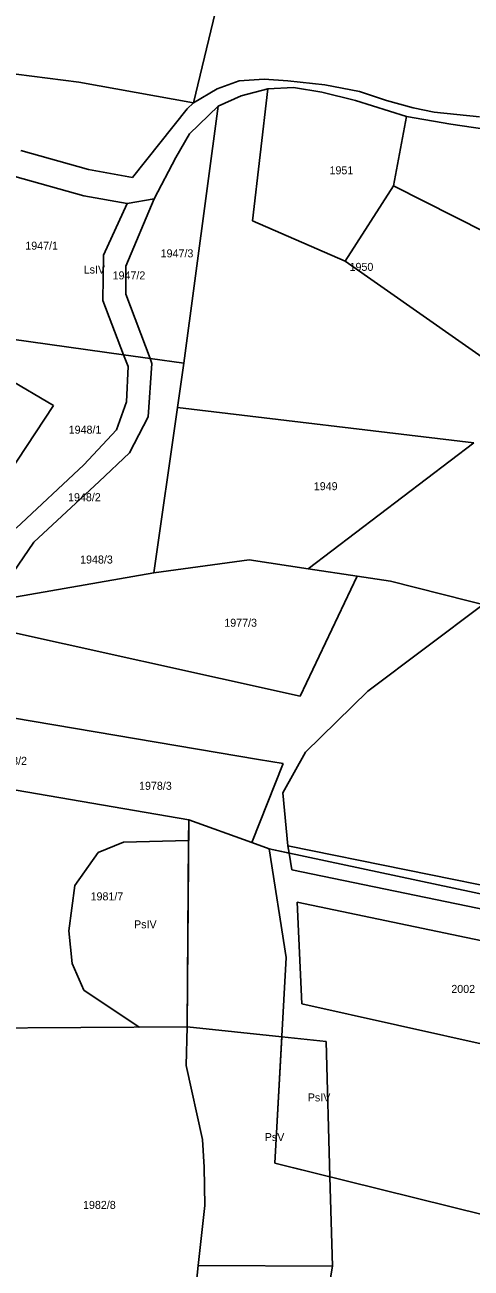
# Model space of a CAD drawing. Extents: x 7498273 to 7499989, y 5499795 to 5500810.
# Drawn here: x 7499197.4 to 7499281.1, y 5499981.8 to 5500214.9 of the extents above; entities that cross this region are included whole.
import ezdxf

# ---------------------------------------------------------------- set-up
doc = ezdxf.new("R2010")
doc.units = 0
for name, color, linetype in [('209-oznaczenie konturu klasyfikacyjnego', 7, 'Continuous'), ('211-numer działki ewidencyjnej', 7, 'Continuous'), ('217-kontur klasyfikacyjny', 7, 'Continuous'), ('218-kontur użytku gruntowego', 7, 'Continuous'), ('219-działka ewidencyjna', 7, 'Continuous')]:
    doc.layers.add(name, color=color, linetype=linetype)

msp = doc.modelspace()

# ---------------------------------------------------------------- linework, layer by layer
at = {"layer": '217-kontur klasyfikacyjny'}
for points in [[(7499229.03, 5500200.27), (7499235.12, 5500225.77)], [(7499186.88, 5500206.79), (7499207.52, 5500204.16)], [(7499207.52, 5500204.16), (7499229.03, 5500200.27)], [(7499229.03, 5500200.27), (7499233.47, 5500202.91)], [(7499233.47, 5500202.91), (7499237.55, 5500204.4)], [(7499237.55, 5500204.4), (7499242.29, 5500204.73)], [(7499242.97, 5500202.88), (7499237.94, 5500201.57)], [(7499242.97, 5500202.88), (7499240.05, 5500178.17)], [(7499242.29, 5500204.73), (7499246.68, 5500204.41)], [(7499247.76, 5500203.13), (7499242.97, 5500202.88)], [(7499246.68, 5500204.41), (7499253.65, 5500203.66)], [(7499253.08, 5500202.29), (7499247.76, 5500203.13)], [(7499253.65, 5500203.66), (7499260.14, 5500202.4)], [(7499229.03, 5500200.27), (7499227.83, 5500199.13)], [(7499237.94, 5500201.57), (7499233.63, 5500199.67)], [(7499259.41, 5500200.69), (7499253.08, 5500202.29)], [(7499268.98, 5500197.72), (7499259.41, 5500200.69)], [(7499260.14, 5500202.4), (7499265.22, 5500200.7)], [(7499265.22, 5500200.7), (7499270.23, 5500199.31)], [(7499227.83, 5500199.13), (7499217.53, 5500186.26)], [(7499233.63, 5500199.67), (7499228.26, 5500194.46)], [(7499270.23, 5500199.31), (7499274.15, 5500198.51)], [(7499274.15, 5500198.51), (7499282.68, 5500197.66)], [(7499277.25, 5500196.3), (7499268.98, 5500197.72)], [(7499283.63, 5500195.35), (7499277.25, 5500196.3)], [(7499228.26, 5500194.46), (7499225.67, 5500190.03)], [(7499209.3, 5500187.74), (7499196.63, 5500191.33)], [(7499225.67, 5500190.03), (7499221.6, 5500182.29)], [(7499208.43, 5500182.85), (7499195.49, 5500186.46)], [(7499217.53, 5500186.26), (7499209.3, 5500187.74)], [(7499216.55, 5500181.37), (7499208.43, 5500182.85)], [(7499221.6, 5500182.29), (7499216.55, 5500181.37)], [(7499240.05, 5500178.17), (7499257.43, 5500170.6)], [(7499257.43, 5500170.6), (7499293.39, 5500145.42)], [(7499283.33, 5500106.19), (7499261.72, 5500089.98)], [(7499261.72, 5500089.98), (7499250, 5500078.53)], [(7499250, 5500078.53), (7499245.79, 5500070.94)], [(7499245.79, 5500070.94), (7499246.69, 5500061)], [(7499228.12, 5500065.83), (7499228.09, 5500062)], [(7499239.94, 5500061.63), (7499228.12, 5500065.83)], [(7499215.88, 5500061.66), (7499211.12, 5500059.72)], [(7499228.09, 5500062), (7499215.88, 5500061.66)], [(7499227.79, 5500027.07), (7499228.09, 5500062)], [(7499243.19, 5500060.39), (7499239.94, 5500061.63)], [(7499246.92, 5500059.6), (7499243.19, 5500060.39)], [(7499246.69, 5500061), (7499291.1, 5500051.95)], [(7499246.69, 5500061), (7499246.92, 5500059.6)], [(7499211.12, 5500059.72), (7499206.77, 5500053.52)], [(7499247.42, 5500056.48), (7499246.92, 5500059.6)], [(7499297.7, 5500046.12), (7499247.42, 5500056.48)], [(7499206.77, 5500053.52), (7499205.6, 5500045.03)], [(7499205.6, 5500045.03), (7499206.22, 5500038.89)], [(7499206.22, 5500038.89), (7499208.41, 5500033.9)], [(7499208.41, 5500033.9), (7499218.8, 5500027.01)], [(7499218.8, 5500027.01), (7499227.79, 5500027.07)], [(7499227.79, 5500027.07), (7499227.65, 5500019.78)], [(7499227.79, 5500027.07), (7499245.56, 5500025.18)], [(7499244.27, 5500001.51), (7499245.56, 5500025.18)], [(7499245.56, 5500025.18), (7499253.87, 5500024.29)], [(7499253.87, 5500024.29), (7499254.6, 5499998.94)], [(7499227.65, 5500019.78), (7499230.67, 5500005.9)], [(7499230.67, 5500005.9), (7499231.02, 5500000.74)], [(7499231.02, 5500000.74), (7499231.16, 5499993.55)], [(7499254.6, 5499998.94), (7499244.27, 5500001.51)], [(7499254.6, 5499998.94), (7499255.09, 5499982.18)], [(7499231.16, 5499993.55), (7499229.91, 5499982.27)], [(7499229.91, 5499982.27), (7499227.42, 5499958.75)], [(7499255.09, 5499982.18), (7499229.91, 5499982.27)]]:
    msp.add_lwpolyline(points, dxfattribs=at)
at = {"layer": '218-kontur użytku gruntowego'}
for points in [[(7499235.12, 5500225.77), (7499229.03, 5500200.27)], [(7499186.88, 5500206.79), (7499207.52, 5500204.16)], [(7499207.52, 5500204.16), (7499229.03, 5500200.27)], [(7499229.03, 5500200.27), (7499233.47, 5500202.91)], [(7499233.47, 5500202.91), (7499237.55, 5500204.4)], [(7499237.55, 5500204.4), (7499242.29, 5500204.73)], [(7499242.97, 5500202.88), (7499237.94, 5500201.57)], [(7499242.97, 5500202.88), (7499240.05, 5500178.17)], [(7499242.29, 5500204.73), (7499246.68, 5500204.41)], [(7499247.76, 5500203.13), (7499242.97, 5500202.88)], [(7499246.68, 5500204.41), (7499253.65, 5500203.66)], [(7499253.08, 5500202.29), (7499247.76, 5500203.13)], [(7499253.65, 5500203.66), (7499260.14, 5500202.4)], [(7499229.03, 5500200.27), (7499227.83, 5500199.13)], [(7499237.94, 5500201.57), (7499233.63, 5500199.67)], [(7499259.41, 5500200.69), (7499253.08, 5500202.29)], [(7499268.98, 5500197.72), (7499259.41, 5500200.69)], [(7499260.14, 5500202.4), (7499265.22, 5500200.7)], [(7499265.22, 5500200.7), (7499270.23, 5500199.31)], [(7499227.83, 5500199.13), (7499217.53, 5500186.26)], [(7499233.63, 5500199.67), (7499228.26, 5500194.46)], [(7499270.23, 5500199.31), (7499274.15, 5500198.51)], [(7499274.15, 5500198.51), (7499282.68, 5500197.66)], [(7499277.25, 5500196.3), (7499268.98, 5500197.72)], [(7499283.63, 5500195.35), (7499277.25, 5500196.3)], [(7499228.26, 5500194.46), (7499225.67, 5500190.03)], [(7499209.3, 5500187.74), (7499196.63, 5500191.33)], [(7499225.67, 5500190.03), (7499221.6, 5500182.29)], [(7499208.43, 5500182.85), (7499195.49, 5500186.46)], [(7499217.53, 5500186.26), (7499209.3, 5500187.74)], [(7499216.55, 5500181.37), (7499208.43, 5500182.85)], [(7499221.6, 5500182.29), (7499216.55, 5500181.37)], [(7499240.05, 5500178.17), (7499257.43, 5500170.6)], [(7499257.43, 5500170.6), (7499293.39, 5500145.42)], [(7499283.33, 5500106.19), (7499261.72, 5500089.98)], [(7499261.72, 5500089.98), (7499250, 5500078.53)], [(7499250, 5500078.53), (7499245.79, 5500070.94)], [(7499245.79, 5500070.94), (7499246.69, 5500061)], [(7499228.12, 5500065.83), (7499228.09, 5500062)], [(7499239.94, 5500061.63), (7499228.12, 5500065.83)], [(7499215.88, 5500061.66), (7499211.12, 5500059.72)], [(7499228.09, 5500062), (7499215.88, 5500061.66)], [(7499228.09, 5500062), (7499227.79, 5500027.07)], [(7499243.19, 5500060.39), (7499239.94, 5500061.63)], [(7499246.92, 5500059.6), (7499243.19, 5500060.39)], [(7499246.69, 5500061), (7499291.1, 5500051.95)], [(7499246.69, 5500061), (7499246.92, 5500059.6)], [(7499211.12, 5500059.72), (7499206.77, 5500053.52)], [(7499246.92, 5500059.6), (7499247.42, 5500056.48)], [(7499247.42, 5500056.48), (7499297.7, 5500046.12)], [(7499206.77, 5500053.52), (7499205.6, 5500045.03)], [(7499205.6, 5500045.03), (7499206.22, 5500038.89)], [(7499206.22, 5500038.89), (7499208.41, 5500033.9)], [(7499208.41, 5500033.9), (7499218.8, 5500027.01)], [(7499218.8, 5500027.01), (7499227.79, 5500027.07)], [(7499227.79, 5500027.07), (7499227.65, 5500019.78)], [(7499227.79, 5500027.07), (7499245.56, 5500025.18)], [(7499245.56, 5500025.18), (7499244.27, 5500001.51)], [(7499253.87, 5500024.29), (7499245.56, 5500025.18)], [(7499254.6, 5499998.94), (7499253.87, 5500024.29)], [(7499227.65, 5500019.78), (7499230.67, 5500005.9)], [(7499230.67, 5500005.9), (7499231.02, 5500000.74)], [(7499231.02, 5500000.74), (7499231.16, 5499993.55)], [(7499244.27, 5500001.51), (7499254.6, 5499998.94)], [(7499254.6, 5499998.94), (7499255.09, 5499982.18)], [(7499231.16, 5499993.55), (7499229.91, 5499982.27)], [(7499229.91, 5499982.27), (7499227.42, 5499958.75)], [(7499255.09, 5499982.18), (7499229.91, 5499982.27)]]:
    msp.add_lwpolyline(points, dxfattribs=at)
at = {"layer": '219-działka ewidencyjna'}
for points in [[(7499229.03, 5500200.27), (7499235.12, 5500225.77)], [(7499186.88, 5500206.79), (7499207.52, 5500204.16)], [(7499207.52, 5500204.16), (7499229.03, 5500200.27)], [(7499229.03, 5500200.27), (7499233.47, 5500202.91)], [(7499233.47, 5500202.91), (7499237.55, 5500204.4)], [(7499237.55, 5500204.4), (7499242.29, 5500204.73)], [(7499237.94, 5500201.57), (7499242.97, 5500202.88)], [(7499240.05, 5500178.17), (7499242.97, 5500202.88)], [(7499242.29, 5500204.73), (7499246.68, 5500204.41)], [(7499247.76, 5500203.13), (7499242.97, 5500202.88)], [(7499246.68, 5500204.41), (7499253.65, 5500203.66)], [(7499247.76, 5500203.13), (7499253.08, 5500202.29)], [(7499253.65, 5500203.66), (7499260.14, 5500202.4)], [(7499229.03, 5500200.27), (7499227.83, 5500199.13)], [(7499233.63, 5500199.67), (7499237.94, 5500201.57)], [(7499253.08, 5500202.29), (7499259.41, 5500200.69)], [(7499259.41, 5500200.69), (7499268.98, 5500197.72)], [(7499260.14, 5500202.4), (7499265.22, 5500200.7)], [(7499265.22, 5500200.7), (7499270.23, 5500199.31)], [(7499217.53, 5500186.26), (7499227.83, 5500199.13)], [(7499227.21, 5500151.46), (7499233.63, 5500199.67)], [(7499233.63, 5500199.67), (7499228.26, 5500194.46)], [(7499270.23, 5500199.31), (7499274.15, 5500198.51)], [(7499274.15, 5500198.51), (7499282.68, 5500197.66)], [(7499268.98, 5500197.72), (7499266.51, 5500184.72)], [(7499268.98, 5500197.72), (7499277.25, 5500196.3)], [(7499277.25, 5500196.3), (7499283.63, 5500195.35)], [(7499225.67, 5500190.03), (7499228.26, 5500194.46)], [(7499196.63, 5500191.33), (7499209.3, 5500187.74)], [(7499221.6, 5500182.29), (7499225.67, 5500190.03)], [(7499195.49, 5500186.46), (7499208.43, 5500182.85)], [(7499209.3, 5500187.74), (7499217.53, 5500186.26)], [(7499257.43, 5500170.6), (7499266.51, 5500184.72)], [(7499295.36, 5500170.12), (7499266.51, 5500184.72)], [(7499208.43, 5500182.85), (7499216.55, 5500181.37)], [(7499221.6, 5500182.29), (7499216.31, 5500169.66)], [(7499216.55, 5500181.37), (7499221.6, 5500182.29)], [(7499216.55, 5500181.37), (7499212.15, 5500171.7)], [(7499240.05, 5500178.17), (7499257.43, 5500170.6)], [(7499211.98, 5500163.24), (7499212.15, 5500171.7)], [(7499257.43, 5500170.6), (7499293.39, 5500145.42)], [(7499216.3, 5500164.43), (7499216.31, 5500169.66)], [(7499215.88, 5500153.04), (7499211.98, 5500163.24)], [(7499220.85, 5500152.35), (7499216.3, 5500164.43)], [(7499187.72, 5500156.98), (7499215.88, 5500153.04)], [(7499215.88, 5500153.04), (7499220.85, 5500152.35)], [(7499215.88, 5500153.04), (7499216.72, 5500150.85)], [(7499220.52, 5500141.42), (7499221.2, 5500151.41)], [(7499220.85, 5500152.35), (7499221.2, 5500151.41)], [(7499227.21, 5500151.46), (7499220.85, 5500152.35)], [(7499226.03, 5500143.16), (7499227.21, 5500151.46)], [(7499216.45, 5500144.23), (7499216.72, 5500150.85)], [(7499194.03, 5500148.64), (7499202.75, 5500143.55)], [(7499194.32, 5500130.74), (7499202.75, 5500143.55)], [(7499214.54, 5500138.99), (7499216.45, 5500144.23)], [(7499221.56, 5500112.14), (7499226.03, 5500143.16)], [(7499226.03, 5500143.16), (7499281.57, 5500136.52)], [(7499216.98, 5500134.65), (7499220.52, 5500141.42)], [(7499208.44, 5500132.43), (7499214.54, 5500138.99)], [(7499250.49, 5500112.93), (7499281.57, 5500136.52)], [(7499211.3, 5500129.27), (7499216.98, 5500134.65)], [(7499195.73, 5500120.55), (7499208.44, 5500132.43)], [(7499199.04, 5500117.9), (7499211.3, 5500129.27)], [(7499192.18, 5500107.88), (7499199.04, 5500117.9)], [(7499239.47, 5500114.6), (7499221.56, 5500112.14)], [(7499239.47, 5500114.6), (7499250.49, 5500112.93)], [(7499221.56, 5500112.14), (7499191.8, 5500106.98)], [(7499250.49, 5500112.93), (7499259.68, 5500111.51)], [(7499259.68, 5500111.51), (7499248.99, 5500089.05)], [(7499259.68, 5500111.51), (7499265.93, 5500110.61)], [(7499265.93, 5500110.61), (7499290.4, 5500104.39)], [(7499248.99, 5500089.05), (7499189.74, 5500102.18)], [(7499241.2, 5500077.18), (7499191.28, 5500085.61)], [(7499245.81, 5500076.38), (7499241.2, 5500077.18)], [(7499239.94, 5500061.63), (7499245.81, 5500076.38)], [(7499228.12, 5500065.83), (7499195.73, 5500071.41)], [(7499227.79, 5500027.07), (7499228.12, 5500065.83)], [(7499228.12, 5500065.83), (7499239.94, 5500061.63)], [(7499239.94, 5500061.63), (7499243.19, 5500060.39)], [(7499243.19, 5500060.39), (7499295.16, 5500049.36)], [(7499243.19, 5500060.39), (7499246.37, 5500040.01)], [(7499248.43, 5500050.43), (7499249.35, 5500031.38)], [(7499248.43, 5500050.43), (7499295.43, 5500040.59)], [(7499244.27, 5500001.51), (7499246.37, 5500040.01)], [(7499249.35, 5500031.38), (7499303.18, 5500019.36)], [(7499187.87, 5500026.8), (7499227.79, 5500027.07)], [(7499227.65, 5500019.78), (7499227.79, 5500027.07)], [(7499227.65, 5500019.78), (7499230.67, 5500005.9)], [(7499230.67, 5500005.9), (7499231.02, 5500000.74)], [(7499231.02, 5500000.74), (7499231.16, 5499993.55)], [(7499244.27, 5500001.51), (7499283.91, 5499991.66)], [(7499229.91, 5499982.27), (7499231.16, 5499993.55)], [(7499227.42, 5499958.75), (7499229.91, 5499982.27)], [(7499229.91, 5499982.27), (7499255.09, 5499982.18)], [(7499241.94, 5499904.45), (7499255.09, 5499982.18)]]:
    msp.add_lwpolyline(points, dxfattribs=at)

# ---------------------------------------------------------------- texts
at = {"layer": '209-oznaczenie konturu klasyfikacyjnego'}
for s, p in [('LsIV', (7499208.4, 5500168.27)), ('PsIV', (7499217.85, 5500045.51)), ('PsIV', (7499250.44, 5500013.06)), ('PsV', (7499242.37, 5500005.63))]:
    msp.add_text(s, height=1.5, dxfattribs=at).set_placement(p)
at = {"layer": '211-numer działki ewidencyjnej'}
for s, p in [('1951', (7499254.52, 5500186.87)), ('1947/1', (7499197.45, 5500172.74)), ('1947/3', (7499222.84, 5500171.3)), ('1950', (7499258.28, 5500168.77)), ('1947/2', (7499213.83, 5500167.17)), ('1948/1', (7499205.59, 5500138.24)), ('1949', (7499251.57, 5500127.65)), ('1948/2', (7499205.47, 5500125.58)), ('1948/3', (7499207.73, 5500113.9)), ('1977/3', (7499234.78, 5500102.05)), ('1978/2', (7499191.63, 5500076.16)), ('1978/3', (7499218.79, 5500071.48)), ('1981/7', (7499209.7, 5500050.75)), ('2002', (7499277.37, 5500033.4)), ('1982/8', (7499208.28, 5499992.91))]:
    msp.add_text(s, height=1.5, dxfattribs=at).set_placement(p)

doc.saveas('drawing.dxf')
